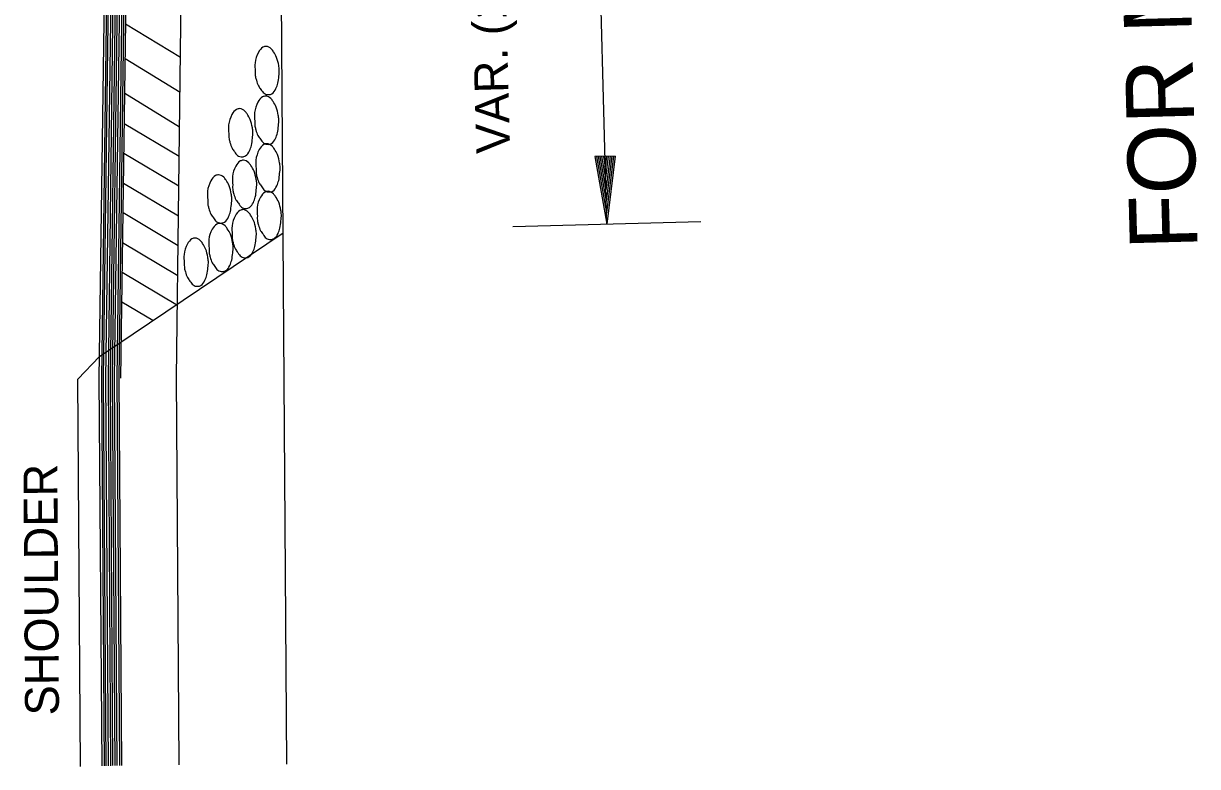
# Model space of a CAD drawing. Extents: x 1926836 to 1933254, y 596317 to 604524.
# Drawn here: x 1933028.7 to 1933236.6, y 596577.6 to 596709.2 of the extents above; entities that cross this region are included whole.
import ezdxf

# ---------------------------------------------------------------- set-up
doc = ezdxf.new("R2010")
doc.units = 0
doc.layers.add('Default', color=7, linetype='Continuous')

msp = doc.modelspace()

# ---------------------------------------------------------------- linework, layer by layer
at = {"layer": 'Default'}
for p, q in [((1933075.31, 596577.97), (1933072.67, 596964.34)), ((1933055.76, 596646.46), (1933058.74, 596882.81)), ((1933043.69, 596646.33), (1933046.68, 596874.69)), ((1933044.05, 596646.34), (1933047.13, 596874.99)), ((1933044.43, 596646.35), (1933047.45, 596875.21)), ((1933044.81, 596646.36), (1933047.89, 596875.5)), ((1933045.23, 596646.38), (1933048.28, 596875.76)), ((1933045.6, 596646.39), (1933048.73, 596876.07)), ((1933045.93, 596646.39), (1933048.99, 596876.24)), ((1933132, 596673.67), (1933126.57, 596875.82)), ((1933042.08, 596646.29), (1933045.12, 596873.64)), ((1933042.52, 596646.3), (1933045.56, 596873.93)), ((1933042.85, 596646.31), (1933045.83, 596874.12)), ((1933043.27, 596646.32), (1933046.29, 596874.43)), ((1933056.47, 596703.16), (1933046.75, 596709.1)), ((1933056.4, 596697), (1933046.69, 596702.92)), ((1933056.32, 596690.84), (1933046.61, 596696.77)), ((1933056.25, 596685.62), (1933046.5, 596691.42)), ((1933056.19, 596680.37), (1933046.45, 596686.14)), ((1933133.47, 596685.72), (1933129.87, 596685.62)), ((1933129.87, 596685.62), (1933132, 596673.67)), ((1933130.17, 596685.63), (1933131.94, 596675.67)), ((1933130.48, 596685.64), (1933131.89, 596677.74)), ((1933130.78, 596685.65), (1933131.83, 596679.74)), ((1933131.08, 596685.65), (1933131.78, 596681.77)), ((1933131.39, 596685.66), (1933131.73, 596683.77)), ((1933131.95, 596685.68), (1933131.73, 596683.77)), ((1933132.25, 596685.68), (1933131.78, 596681.77)), ((1933132.56, 596685.69), (1933131.83, 596679.74)), ((1933132.86, 596685.7), (1933131.89, 596677.74)), ((1933133.17, 596685.71), (1933131.94, 596675.67)), ((1933133.47, 596685.72), (1933132, 596673.67)), ((1933056.12, 596675.07), (1933046.36, 596680.88)), ((1933056.05, 596669.78), (1933046.33, 596675.63)), ((1933115.32, 596673.23), (1933148.67, 596674.12)), ((1933042.12, 596650.21), (1933074.66, 596672.13)), ((1933055.99, 596664.51), (1933046.22, 596670.34)), ((1933055.92, 596659.26), (1933046.16, 596665.08)), ((1933051.56, 596656.57), (1933046.08, 596659.83)), ((1933042.57, 596577.67), (1933042.08, 596646.29)), ((1933042.99, 596577.68), (1933042.52, 596646.3)), ((1933043.31, 596577.69), (1933042.85, 596646.31)), ((1933043.72, 596577.7), (1933043.27, 596646.32)), ((1933044.12, 596577.71), (1933043.69, 596646.33)), ((1933044.5, 596577.72), (1933044.05, 596646.34)), ((1933044.89, 596577.73), (1933044.43, 596646.35)), ((1933045.28, 596577.74), (1933044.81, 596646.36)), ((1933045.71, 596577.75), (1933045.23, 596646.38)), ((1933046.09, 596577.76), (1933045.6, 596646.39)), ((1933056.25, 596577.84), (1933055.76, 596646.46))]:
    msp.add_line(p, q, dxfattribs=at)
msp.add_lwpolyline([(1933038.75, 596577.57), (1933038.28, 596646.19), (1933042.12, 596650.21)], dxfattribs=at)
for points in [[(1933069.72, 596700.72), (1933069.69, 596702.25), (1933070.28, 596704.08), (1933071.08, 596705), (1933071.62, 596705.13), (1933072.55, 596704.7), (1933072.96, 596704.19), (1933073.5, 596703.2), (1933073.88, 596701.75), (1933073.98, 596700.99), (1933073.9, 596699.88), (1933073.73, 596698.62), (1933073.38, 596697.66), (1933072.67, 596696.76), (1933072.1, 596696.59), (1933071.27, 596696.83), (1933070.72, 596697.51), (1933070.29, 596698.14), (1933069.91, 596699.15), (1933069.75, 596699.78), (1933069.72, 596700.72)], [(1933069.63, 596691.92), (1933069.6, 596693.45), (1933070.19, 596695.28), (1933071, 596696.19), (1933071.54, 596696.33), (1933072.47, 596695.89), (1933072.87, 596695.38), (1933073.42, 596694.4), (1933073.8, 596692.95), (1933073.9, 596692.19), (1933073.82, 596691.08), (1933073.64, 596689.81), (1933073.3, 596688.85), (1933072.59, 596687.95), (1933072.02, 596687.79), (1933071.19, 596688.03), (1933070.64, 596688.71), (1933070.2, 596689.34), (1933069.83, 596690.35), (1933069.67, 596690.98), (1933069.63, 596691.92)], [(1933065.03, 596689.7), (1933065, 596691.23), (1933065.59, 596693.07), (1933066.4, 596693.98), (1933066.94, 596694.11), (1933067.87, 596693.68), (1933068.27, 596693.17), (1933068.82, 596692.18), (1933069.2, 596690.73), (1933069.3, 596689.97), (1933069.22, 596688.86), (1933069.04, 596687.6), (1933068.7, 596686.64), (1933067.99, 596685.74), (1933067.42, 596685.57), (1933066.59, 596685.81), (1933066.04, 596686.5), (1933065.6, 596687.12), (1933065.23, 596688.13), (1933065.07, 596688.76), (1933065.03, 596689.7)], [(1933069.86, 596683.48), (1933069.83, 596685.01), (1933070.42, 596686.85), (1933071.23, 596687.76), (1933071.76, 596687.89), (1933072.7, 596687.46), (1933073.1, 596686.95), (1933073.65, 596685.96), (1933074.02, 596684.51), (1933074.12, 596683.75), (1933074.04, 596682.64), (1933073.87, 596681.38), (1933073.52, 596680.42), (1933072.82, 596679.52), (1933072.24, 596679.35), (1933071.42, 596679.59), (1933070.87, 596680.28), (1933070.43, 596680.9), (1933070.05, 596681.91), (1933069.9, 596682.54), (1933069.86, 596683.48)], [(1933065.72, 596680.56), (1933065.69, 596682.09), (1933066.28, 596683.92), (1933067.08, 596684.84), (1933067.62, 596684.97), (1933068.55, 596684.54), (1933068.96, 596684.03), (1933069.5, 596683.04), (1933069.88, 596681.59), (1933069.98, 596680.83), (1933069.9, 596679.72), (1933069.73, 596678.45), (1933069.38, 596677.49), (1933068.68, 596676.6), (1933068.1, 596676.43), (1933067.27, 596676.67), (1933066.72, 596677.35), (1933066.29, 596677.98), (1933065.91, 596678.99), (1933065.75, 596679.62), (1933065.72, 596680.56)], [(1933061.3, 596677.98), (1933061.27, 596679.51), (1933061.86, 596681.35), (1933062.67, 596682.26), (1933063.2, 596682.39), (1933064.14, 596681.96), (1933064.54, 596681.45), (1933065.09, 596680.46), (1933065.47, 596679.01), (1933065.57, 596678.26), (1933065.49, 596677.14), (1933065.31, 596675.88), (1933064.97, 596674.92), (1933064.26, 596674.02), (1933063.68, 596673.85), (1933062.86, 596674.09), (1933062.31, 596674.78), (1933061.87, 596675.41), (1933061.49, 596676.42), (1933061.34, 596677.04), (1933061.3, 596677.98)], [(1933070.09, 596675.05), (1933070.06, 596676.58), (1933070.65, 596678.42), (1933071.45, 596679.33), (1933071.99, 596679.47), (1933072.92, 596679.03), (1933073.33, 596678.52), (1933073.87, 596677.54), (1933074.25, 596676.08), (1933074.35, 596675.33), (1933074.27, 596674.21), (1933074.09, 596672.95), (1933073.75, 596671.99), (1933073.04, 596671.09), (1933072.47, 596670.93), (1933071.64, 596671.16), (1933071.09, 596671.85), (1933070.66, 596672.48), (1933070.28, 596673.49), (1933070.12, 596674.11), (1933070.09, 596675.05)], [(1933065.64, 596671.8), (1933065.61, 596673.33), (1933066.2, 596675.17), (1933067.01, 596676.08), (1933067.54, 596676.22), (1933068.48, 596675.78), (1933068.88, 596675.27), (1933069.43, 596674.28), (1933069.81, 596672.83), (1933069.91, 596672.08), (1933069.83, 596670.96), (1933069.65, 596669.7), (1933069.31, 596668.74), (1933068.6, 596667.84), (1933068.02, 596667.67), (1933067.2, 596667.91), (1933066.65, 596668.6), (1933066.21, 596669.23), (1933065.83, 596670.24), (1933065.68, 596670.86), (1933065.64, 596671.8)], [(1933061.53, 596669.38), (1933061.5, 596670.91), (1933062.09, 596672.74), (1933062.9, 596673.65), (1933063.44, 596673.79), (1933064.37, 596673.35), (1933064.77, 596672.84), (1933065.32, 596671.86), (1933065.7, 596670.41), (1933065.8, 596669.65), (1933065.72, 596668.54), (1933065.54, 596667.27), (1933065.2, 596666.31), (1933064.49, 596665.41), (1933063.91, 596665.25), (1933063.09, 596665.49), (1933062.54, 596666.17), (1933062.1, 596666.8), (1933061.73, 596667.81), (1933061.57, 596668.44), (1933061.53, 596669.38)], [(1933057.14, 596666.77), (1933057.11, 596668.3), (1933057.7, 596670.14), (1933058.51, 596671.05), (1933059.04, 596671.18), (1933059.98, 596670.75), (1933060.38, 596670.24), (1933060.93, 596669.25), (1933061.31, 596667.8), (1933061.41, 596667.04), (1933061.33, 596665.93), (1933061.15, 596664.67), (1933060.81, 596663.71), (1933060.1, 596662.81), (1933059.52, 596662.64), (1933058.7, 596662.88), (1933058.15, 596663.56), (1933057.71, 596664.19), (1933057.33, 596665.2), (1933057.18, 596665.83), (1933057.14, 596666.77)]]:
    msp.add_spline(points, degree=3, dxfattribs=at)

# ---------------------------------------------------------------- texts
for s, height, rotation, p in [('FOR MAINTENANCE OF TRAFFIC', 12, 91.5377, (1933236.67, 596669.28)), ('VAR. (12\'-10" NORM.) AGGREGATE', 6, 91.5377, (1933114.88, 596686.23)), ('SHOULDER', 6, 90.3919, (1933034.95, 596586.63))]:
    msp.add_text(s, height=height, rotation=rotation, dxfattribs=at).set_placement(p)

doc.saveas('drawing.dxf')
